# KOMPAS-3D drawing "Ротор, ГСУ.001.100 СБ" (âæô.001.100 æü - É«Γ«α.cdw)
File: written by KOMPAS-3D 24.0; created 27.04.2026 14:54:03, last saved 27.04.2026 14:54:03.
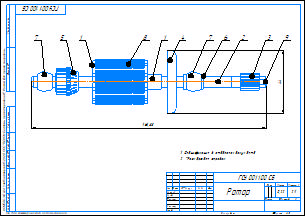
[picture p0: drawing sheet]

Document properties: Автор: User7; Форматы листов документа: A4; Полное имя файла: ГСУ.001.100 СБ - Ротор.a3d; Масса: 0.220757; Наименование: Ротор; Количество листов документа: 1

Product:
- Component [detail]: Звездочка  | designation ГСУ.001.101  | qty 1  | pos. 1  | Масса: 0.070368; Автор: User7; source file: ГСУ.001.101 - Звездочка.m3d
- Component [detail]: Вал ротора  | designation ГСУ.001.102  | qty 1  | pos. 2  | Масса: 0.060496; Автор: User7; source file: ГСУ.001.102 - Вал ротора.m3d
- Component [detail]: Шестеренка  | designation ГСУ.001.103  | qty 1  | pos. 3  | Масса: 0.004863; Автор: User7; source file: ГСУ.001.103 - Шестеренка.m3d
- Component [detail]: Пропеллер  | designation ГСУ.001.104  | qty 1  | pos. 4  | Масса: 0.033692; Автор: User7; source file: ГСУ.001.104 - Пропеллер.m3d
- Component [detail]: Коллектор  | designation ГСУ.001.105  | qty 1  | pos. 5  | Масса: 0.01991; Автор: User7; source file: ГСУ.001.105 - Коллектор.m3d
- Component [detail]: Шайба  | designation ГСУ.001.106  | qty 2  | pos. 6  | Масса: 0.000703; Автор: User7; source file: ГСУ.001.106 - Шайба.m3d
- Component [detail]: Втулка  | designation ГСУ.001.107  | qty 2  | pos. 7  | Масса: 0.00612; Автор: User7; source file: ГСУ.001.107 - Втулка.m3d
- Component [detail]: Пластина  | designation ГСУ.001.108  | qty 10  | pos. 8  | Масса: 0.00166; Автор: User7; source file: ГСУ.001.108 - Пластина.m3d
- Component [standard]: Гайка М4-6H ГОСТ 15523-70  | qty 1  | pos. 9  | Масса: 0.001183; Раздел спецификации: Стандартные изделия; Рассекать на разрезах: no
- Part/product: Ротор  | designation ГСУ.001.100 СБ
    Масса: 0.220757
    Форматы листов документа: A4
    source file: ГСУ.001.100 СБ - Ротор.spw

Referenced files in C:\Users\User7\Desktop\Двигатель мясорубки\: ГСУ.001.101 - Звездочка.m3d, ГСУ.001.102 - Вал ротора.m3d, ГСУ.001.103 - Шестеренка.m3d, ГСУ.001.104 - Пропеллер.m3d, ГСУ.001.105 - Коллектор.m3d, ГСУ.001.106 - Шайба.m3d, ГСУ.001.107 - Втулка.m3d, ГСУ.001.108 - Пластина.m3d, ГСУ.001.100 СБ - Ротор.a3d
Referenced files in C:\Program Files\ASCON\KOMPAS-3D v21\Libs\PARTLib\DATA\vault\Methods\Kompas\3D\: PLib_Nut_OST92_900.m3d
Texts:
  Программные изделия  и базы данных
  Принадлежности
  Приспособления
  Упаковка
  ГСУ.001.101
  Звездочка
  ГСУ.001.102
  Вал ротора
  ГСУ.001.103
  Шестеренка
  ГСУ.001.104
  Пропеллер
  ГСУ.001.105
  Коллектор
  ГСУ.001.106
  Шайба
  ГСУ.001.107
  Втулка
  ГСУ.001.108
  Пластина
  Гайка М4-6H ГОСТ 15523-70
  Крепежное изделие ГОСТ
  Гайка
  ГОСТ
  ГСУ.001.100 СБ
  Ротор
  ГСУ.001.101 Звездочка
  ГСУ.001.102 Вал ротора
  ГСУ.001.103 Шестеренка
  ГСУ.001.104 Пропеллер
  ГСУ.001.105 Коллектор
  ГСУ.001.106 Шайба
  ГСУ.001.107 Втулка
  ГСУ.001.108 Пластина
  ГСУ.001.100 СБ Ротор
Dimensions and other numbers on the sheet: 1; 2; 3; 4; 5; 6; 7; 8; 10; 9; 58; 40Х; 019; 2:1; 0; 0,22

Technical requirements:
  Спецификация в отдельном документе
  GOST Type AU
  *Размеры для справок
